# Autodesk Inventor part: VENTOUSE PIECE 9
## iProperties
Created: 2004-11
Part Number: VENTOUSE PIECE 9
Document SubType Name: Modeling
Designer: Bruno
Manufacturer: Standard
Standards Organization: Custom
Author: Bruno
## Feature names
1. Base1
